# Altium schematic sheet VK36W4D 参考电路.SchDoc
size A4
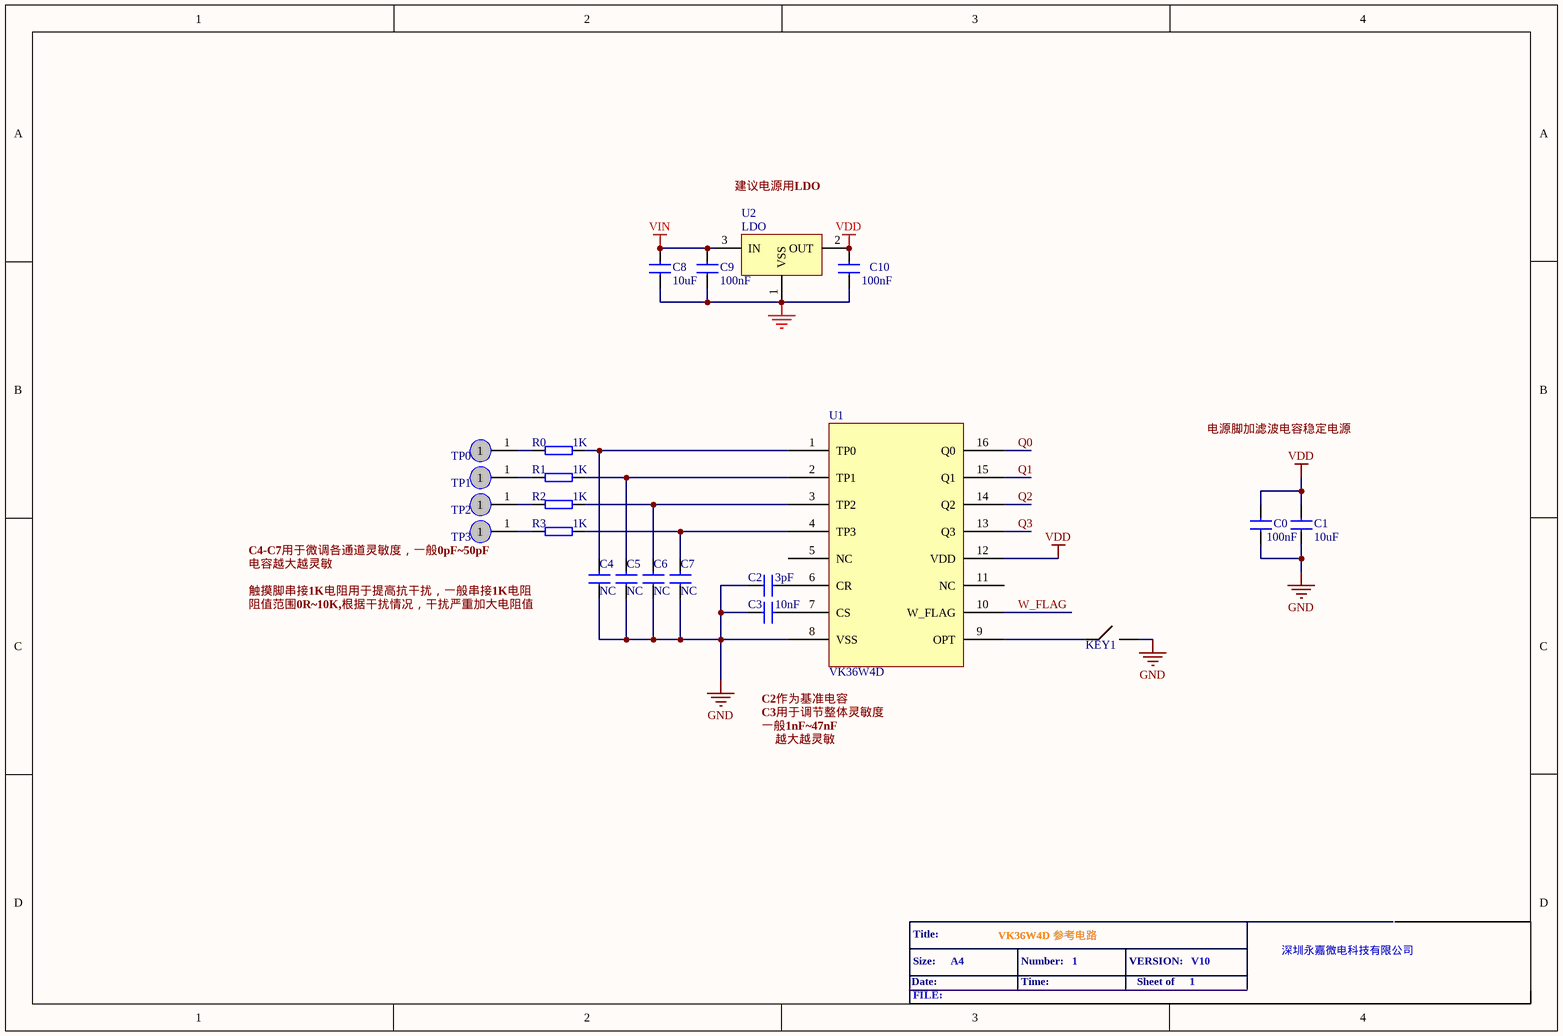
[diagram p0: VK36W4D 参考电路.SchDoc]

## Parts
C0  100nF  [0603-C]
C1  10uF  [0603-C]
C2  value 3pF  [0603-C]  (hidden comment: 10uF)
C3  value 10nF  [0603-C]  (hidden comment: 10uF)
C4  value NC  [0603-C]  (hidden comment: 10uF)
C5  value NC  [0603-C]  (hidden comment: 10uF)
C6  value NC  [0603-C]  (hidden comment: 10uF)
C7  value NC  [0603-C]  (hidden comment: 10uF)
C8  10uF  [0805-C]
C9  100nF  [0805-C]
C10  100nF  [0805-C]
KEY1  单刀单掷开关  (value not drawn)
R0  1K  [0603-R]
R1  1K  [0603-R]
R2  1K  [0603-R]
R3  1K  [0603-R]
TP0  TPAD  [TP-PAD0]  (value not drawn)
TP1  TPAD  [TP-PAD0]  (value not drawn)
TP2  TPAD  [TP-PAD0]  (value not drawn)
TP3  TPAD  [TP-PAD0]  (value not drawn)
U1  VK36W4D
U2  LDO  [SOT-23]

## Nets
GND: C0.2 C1.2 C2.2 C3.2 C4.1 C5.1 C6.1 C7.1 C8.2 C9.2 C10.2 U1.8(VSS) U2.1(VSS)
VDD: C0.1 C1.1 C10.1 U1.12(VDD) U2.2(OUT)
VIN: C8.1 C9.1 U2.3(IN)
Q0: U1.16(Q0)
Q1: U1.15(Q1)
Q2: U1.14(Q2)
Q3: U1.13(Q3)
W_FLAG: U1.10(W_FLAG)
NetC2_1: C2.1 U1.6(CR)
NetC3_1: C3.1 U1.7(CS)
NetC4_2: C4.2 R0.2 U1.1(TP0)
NetC5_2: C5.2 R1.1 U1.2(TP1)
NetC6_2: C6.2 R2.1 U1.3(TP2)
NetC7_2: C7.2 R3.1 U1.4(TP3)
NetR0_1: R0.1 TP0.1
NetR1_2: R1.2 TP1.1
NetR2_2: R2.2 TP2.1
NetR3_2: R3.2 TP3.1

Not connected (* = marked no-connect by the designer): U1 5(NC) 9(OPT) 11(NC)

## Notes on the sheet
- 建议电源用LDO
- 电源脚加滤波电容稳定电源
- C4-C7用于微调各通道灵敏度，一般0pF~50pF
- 电容越大越灵敏
- 触摸脚串接1K电阻用于提高抗干扰，一般串接1K电阻
- 阻值范围0R
  0K,根据干扰情况，干扰严重加大电阻值
- C3用于调节整体灵敏度
- C2作为基准电容
- 一般1nF~47nF
- 越大越灵敏
- Date:
- Title:
- Size:
- A4
- VK36W4D 参考电路
- Number:
- Time:
- 1
- VERSION:
- Sheet of
- V10
- 深圳永嘉微电科技有限公司
- FILE:

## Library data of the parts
C0-C10 = CAP: Capacitor
R0-R3 = RES: Resistor
TP0-TP3 = TPAD: TESTING
U2 = V6206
